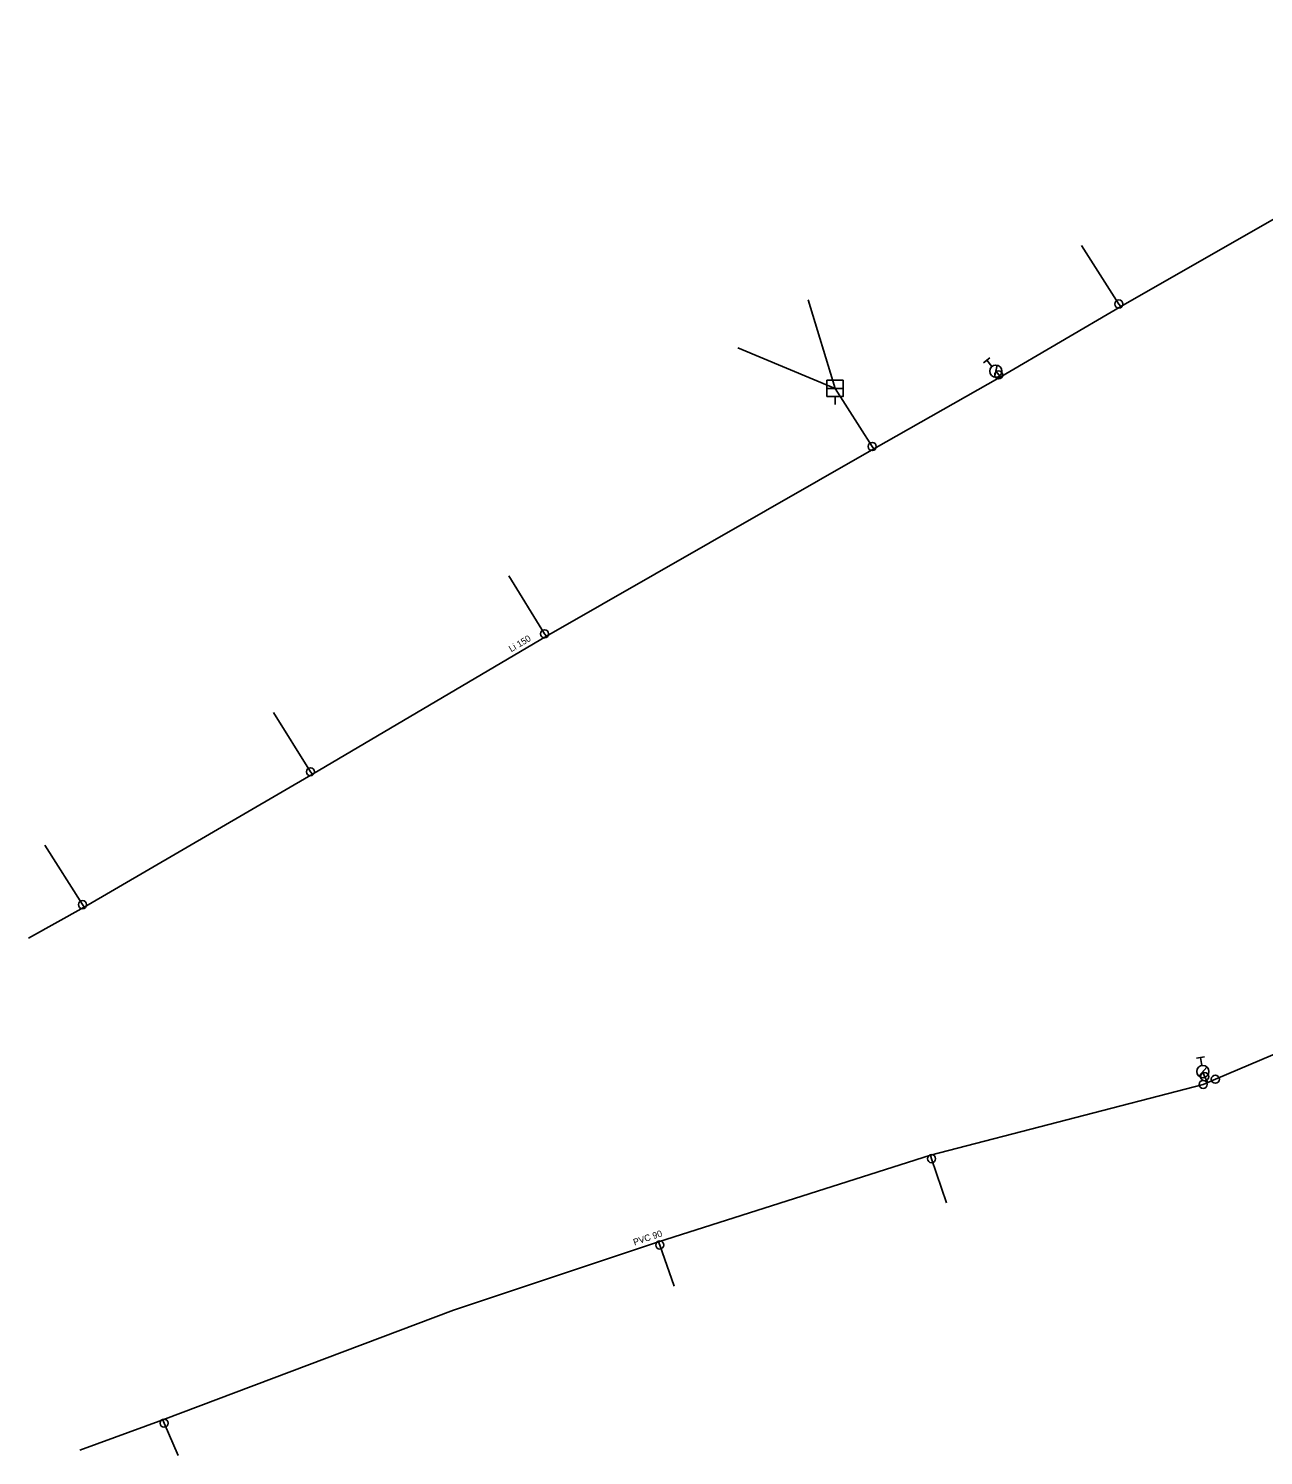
# Model space of a CAD drawing. Extents: x -783658 to -783200, y -1065250 to -1064865.
# Drawn here: x -783657.6 to -783581.5, y -1065176.1 to -1065088.1 of the extents above; entities that cross this region are included whole.
import ezdxf

# ---------------------------------------------------------------- set-up
doc = ezdxf.new("R2010")
doc.units = 0
for name, color, linetype in [('Hydranty', 7, 'Continuous'), ('Popis vodovodních řadů', 7, 'Continuous'), ('Vod přípojky-voda pitná', 7, 'Continuous'), ('Vodovodní řad', 7, 'Continuous'), ('Vodovodní šachty', 7, 'Continuous'), ('Vodovodní šoupata', 7, 'Continuous')]:
    doc.layers.add(name, color=color, linetype=linetype)

msp = doc.modelspace()

# ---------------------------------------------------------------- linework, layer by layer
at = {"layer": 'Hydranty'}
for p, q in [((-783598.724, -1065108.73), (-783598.341, -1065108.409)), ((-783598.211, -1065108.953), (-783598.532, -1065108.57)), ((-783598.047, -1065109.606), (-783597.892, -1065108.872)), ((-783585.608, -1065151.592), (-783585.116, -1065151.505)), ((-783585.275, -1065152.041), (-783585.362, -1065151.548)), ((-783585.459, -1065152.689), (-783584.959, -1065152.13))]:
    msp.add_line(p, q, dxfattribs=at)
for centre in [(-783597.97, -1065109.24), (-783585.21, -1065152.41)]:
    msp.add_circle(centre, 0.375, dxfattribs=at)
at = {"layer": 'Vod přípojky-voda pitná'}
for points in [[(-783590.27, -1065105.26), (-783590.39, -1065105.1), (-783592.69, -1065101.5)], [(-783607.88, -1065110.3), (-783609.54, -1065104.84)], [(-783607.88, -1065110.3), (-783613.87, -1065107.81)], [(-783605.48, -1065114.03), (-783605.59, -1065113.88), (-783607.88, -1065110.3)], [(-783625.67, -1065125.58), (-783625.78, -1065125.43), (-783627.98, -1065121.86)], [(-783640.09, -1065134.08), (-783640.21, -1065133.93), (-783642.48, -1065130.27)], [(-783654.15, -1065142.27), (-783654.26, -1065142.12), (-783656.58, -1065138.46)], [(-783602, -1065157.56), (-783601.93, -1065157.78), (-783601.01, -1065160.5)], [(-783618.75, -1065162.9), (-783618.68, -1065163.1), (-783617.79, -1065165.64)], [(-783649.31, -1065173.88), (-783649.23, -1065174.08), (-783648.37, -1065176.07)]]:
    msp.add_lwpolyline(points, dxfattribs=at)
at = {"layer": 'Vodovodní řad'}
for points in [[(-783597.7, -1065109.6), (-783590.27, -1065105.26), (-783560.3, -1065088.12)], [(-783584.44, -1065152.88), (-783566.77, -1065145.37), (-783545.99, -1065135.02), (-783528.71, -1065127.46), (-783511.16, -1065113.31), (-783500.9, -1065104.99), (-783490.8, -1065102.94)], [(-783657.583, -1065144.195), (-783654.15, -1065142.27), (-783640.09, -1065134.08), (-783625.67, -1065125.58), (-783605.48, -1065114.03), (-783597.7, -1065109.6)], [(-783597.97, -1065109.24), (-783597.79, -1065109.47)], [(-783597.79, -1065109.47), (-783597.7, -1065109.6)], [(-783585.21, -1065152.41), (-783585.1, -1065152.72)], [(-783585.1, -1065152.72), (-783584.91, -1065153.08)], [(-783654.423, -1065175.739), (-783649.31, -1065173.88), (-783631.39, -1065167.11), (-783618.75, -1065162.9), (-783602, -1065157.56), (-783585.19, -1065153.2)], [(-783585.19, -1065153.2), (-783584.91, -1065153.08)], [(-783584.91, -1065153.08), (-783584.44, -1065152.88)]]:
    msp.add_lwpolyline(points, dxfattribs=at)
at = {"layer": 'Vodovodní šachty'}
msp.add_line((-783607.88, -1065111.3), (-783607.88, -1065110.8), dxfattribs=at)
msp.add_lwpolyline([(-783608.38, -1065110.3), (-783608.38, -1065109.8), (-783607.38, -1065109.8), (-783607.38, -1065110.3)], dxfattribs=at)
msp.add_lwpolyline([(-783608.38, -1065110.8), (-783607.38, -1065110.8), (-783607.38, -1065110.3), (-783608.38, -1065110.3)], close=True, dxfattribs=at)
at = {"layer": 'Vodovodní šoupata'}
for centre in [(-783590.39, -1065105.1), (-783597.79, -1065109.47), (-783605.59, -1065113.88), (-783625.78, -1065125.43), (-783640.21, -1065133.93), (-783654.26, -1065142.12), (-783585.1, -1065152.72), (-783584.44, -1065152.88), (-783585.19, -1065153.2), (-783601.93, -1065157.78), (-783618.68, -1065163.1), (-783649.23, -1065174.08)]:
    msp.add_circle(centre, 0.25, dxfattribs=at)

# ---------------------------------------------------------------- texts
at = {"layer": 'Popis vodovodních řadů'}
for s, rotation, p in [('Li 150', 30.51761, (-783627.836, -1065126.566)), ('PVC 90', 18.42135, (-783620.239, -1065163.132))]:
    msp.add_text(s, height=0.4, rotation=rotation, dxfattribs=at).set_placement(p)

doc.saveas('drawing.dxf')
